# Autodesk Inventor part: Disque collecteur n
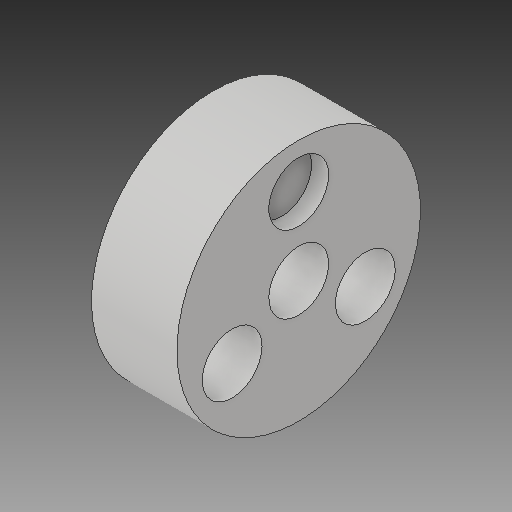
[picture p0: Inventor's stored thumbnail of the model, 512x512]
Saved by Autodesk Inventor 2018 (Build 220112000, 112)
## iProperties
Created: 2017-03
Part Number: Disque collecteur n
Material: Generic
Document SubType Name: Modeling
Designer: thierry.jost
Density: 1 g/cm^3
Appearance: Default
Author: thierry.jost
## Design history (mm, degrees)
sketch "Sketch1"
  geometry: C1 r 14.25 at (0, 0); 1 further point
  constraints: 1 centre point, 1 coincident
  dimensions: "d0" = 28.5 diameter of C1
extrude "Extrusion1" new body sketch "Sketch1" distance "d1" = 10; taper "d2" = 0 deg
sketch "Sketch2"
  geometry: 2 further points
  dimensions: "d3" = 0 horizontal distance of point (0, 0) point (0, 9); "d4" = 9 distance of point (0, 9) point (0, 0)
hole "Hole1" sketch "Sketch2" at (0, 9) diameter "d5" = 7; stored, may be unused: countersink angle "d9" = 90 deg, drill point angle "d11" = 0 deg; dims "d6" = 6, "d7" = 7, "d8" = 2, "d10" = 2
hole "Hole2" diameter "d14" = 7; stored, may be unused: countersink angle "d18" = 90 deg, drill point angle "d20" = 118 deg; dims "d12" = 10, "d13" = 10, "d15" = 6, "d16" = 7, "d17" = 2, "d19" = 8
sketch "Sketch3"
  geometry: L1 (0, 0)-(-7.794, -4.5); L2 (0, 0)-(0, -16.389)
  constraints: 4 end point, 1 vertical
  dimensions: "d21" = 9 distance of L1.start L1.end; "d22" = 60 deg angle of L1 L2
hole "Hole3" sketch "Sketch3" at (-7.794, -4.5) diameter "d23" = 7; stored, may be unused: countersink angle "d27" = 90 deg, drill point angle "d29" = 118 deg; dims "d24" = 6, "d25" = 7, "d26" = 2, "d28" = 8
pattern_circular "Circular Pattern1" dims angle "d31" = 120 deg
body "Solid1"
